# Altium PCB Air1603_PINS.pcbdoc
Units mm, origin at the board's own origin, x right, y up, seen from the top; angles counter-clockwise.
Board outline 36.6 x 36.59 mm, 2 copper layers (Top Layer, Bottom Layer); 1 components, 0 nets, 64 pads, 0 vias.
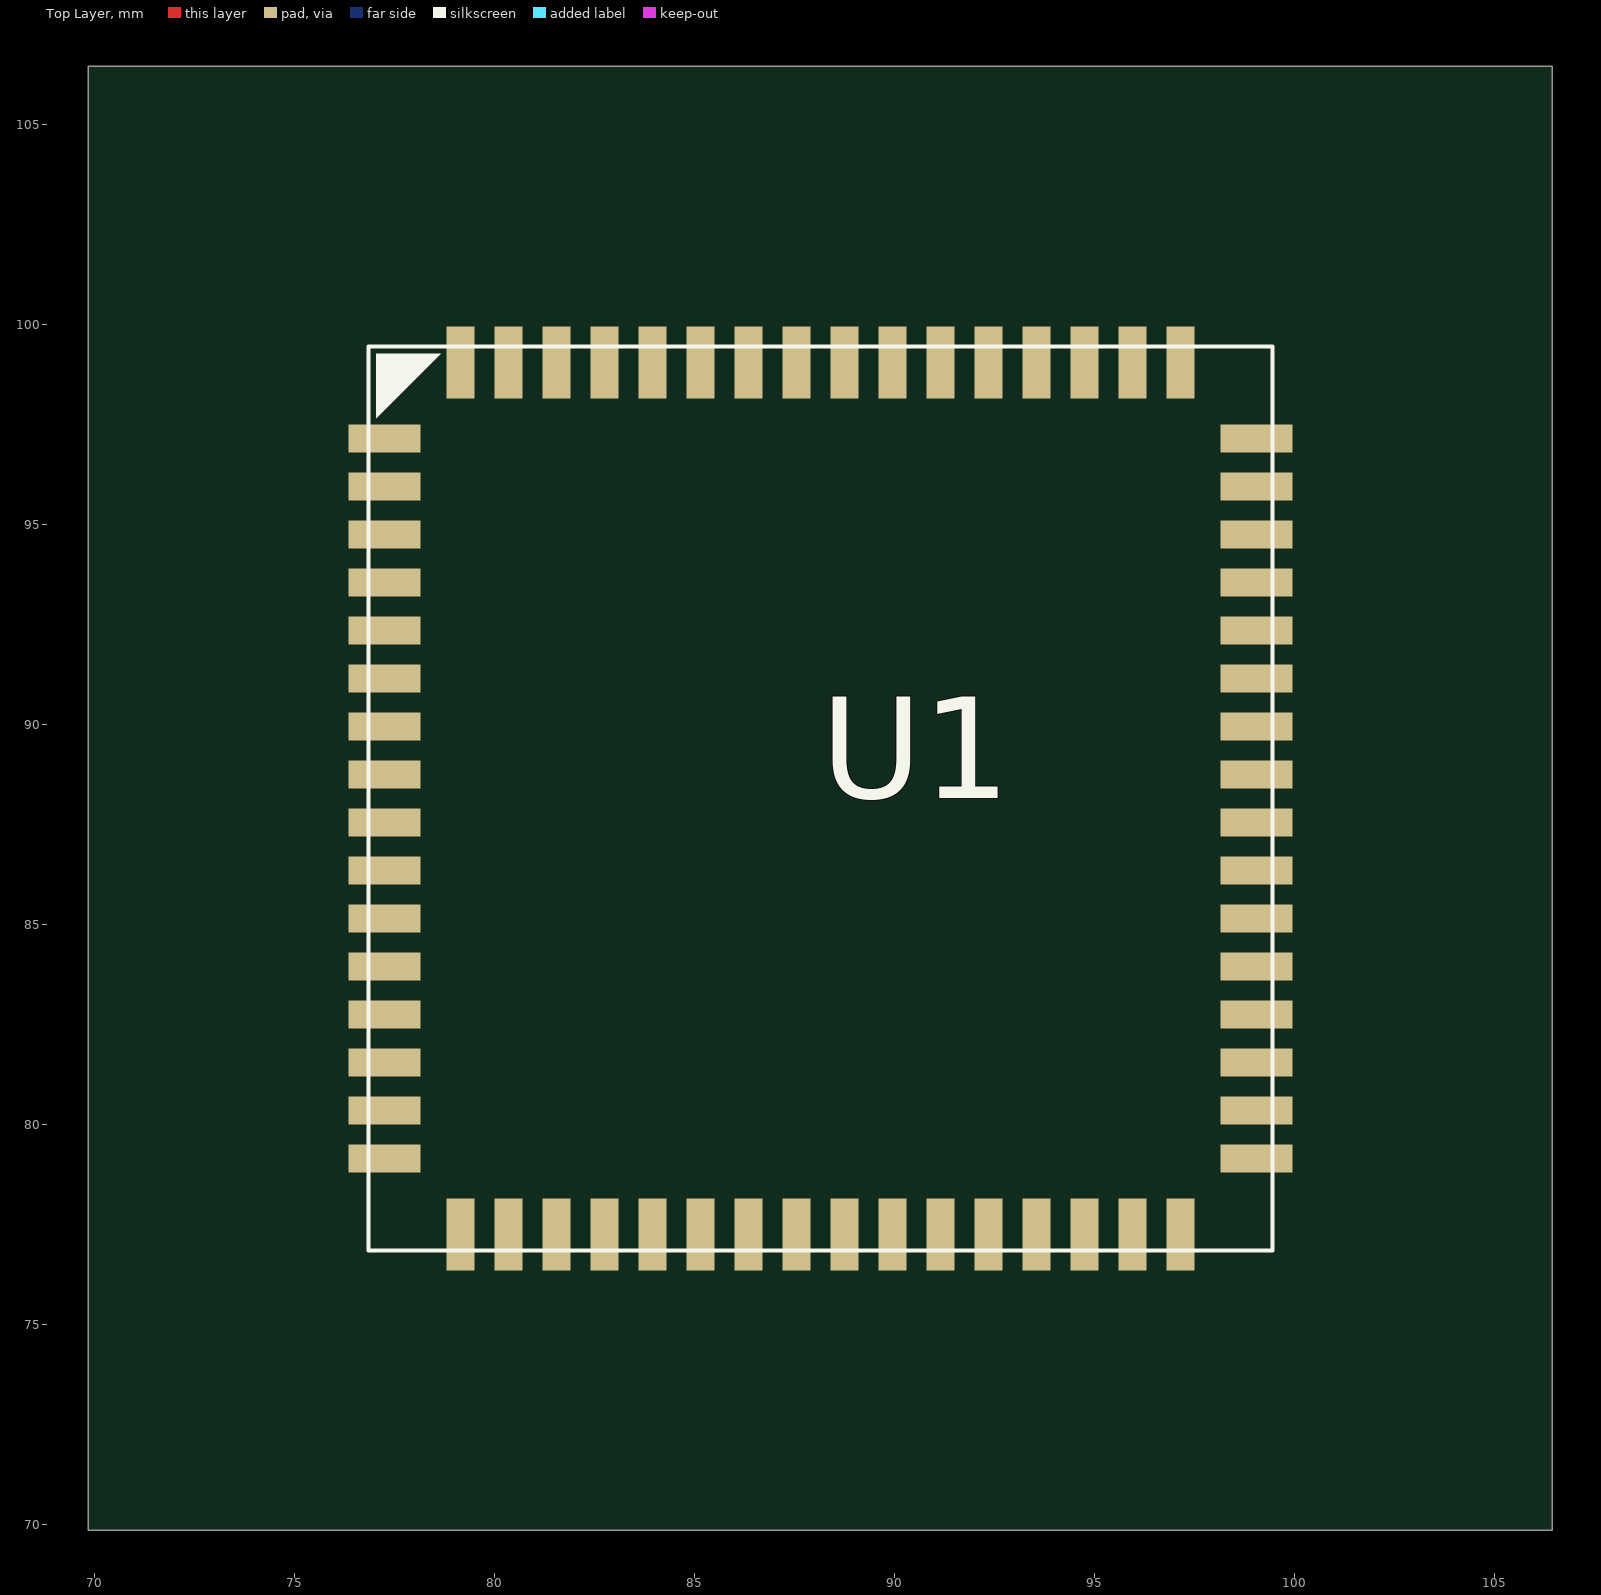
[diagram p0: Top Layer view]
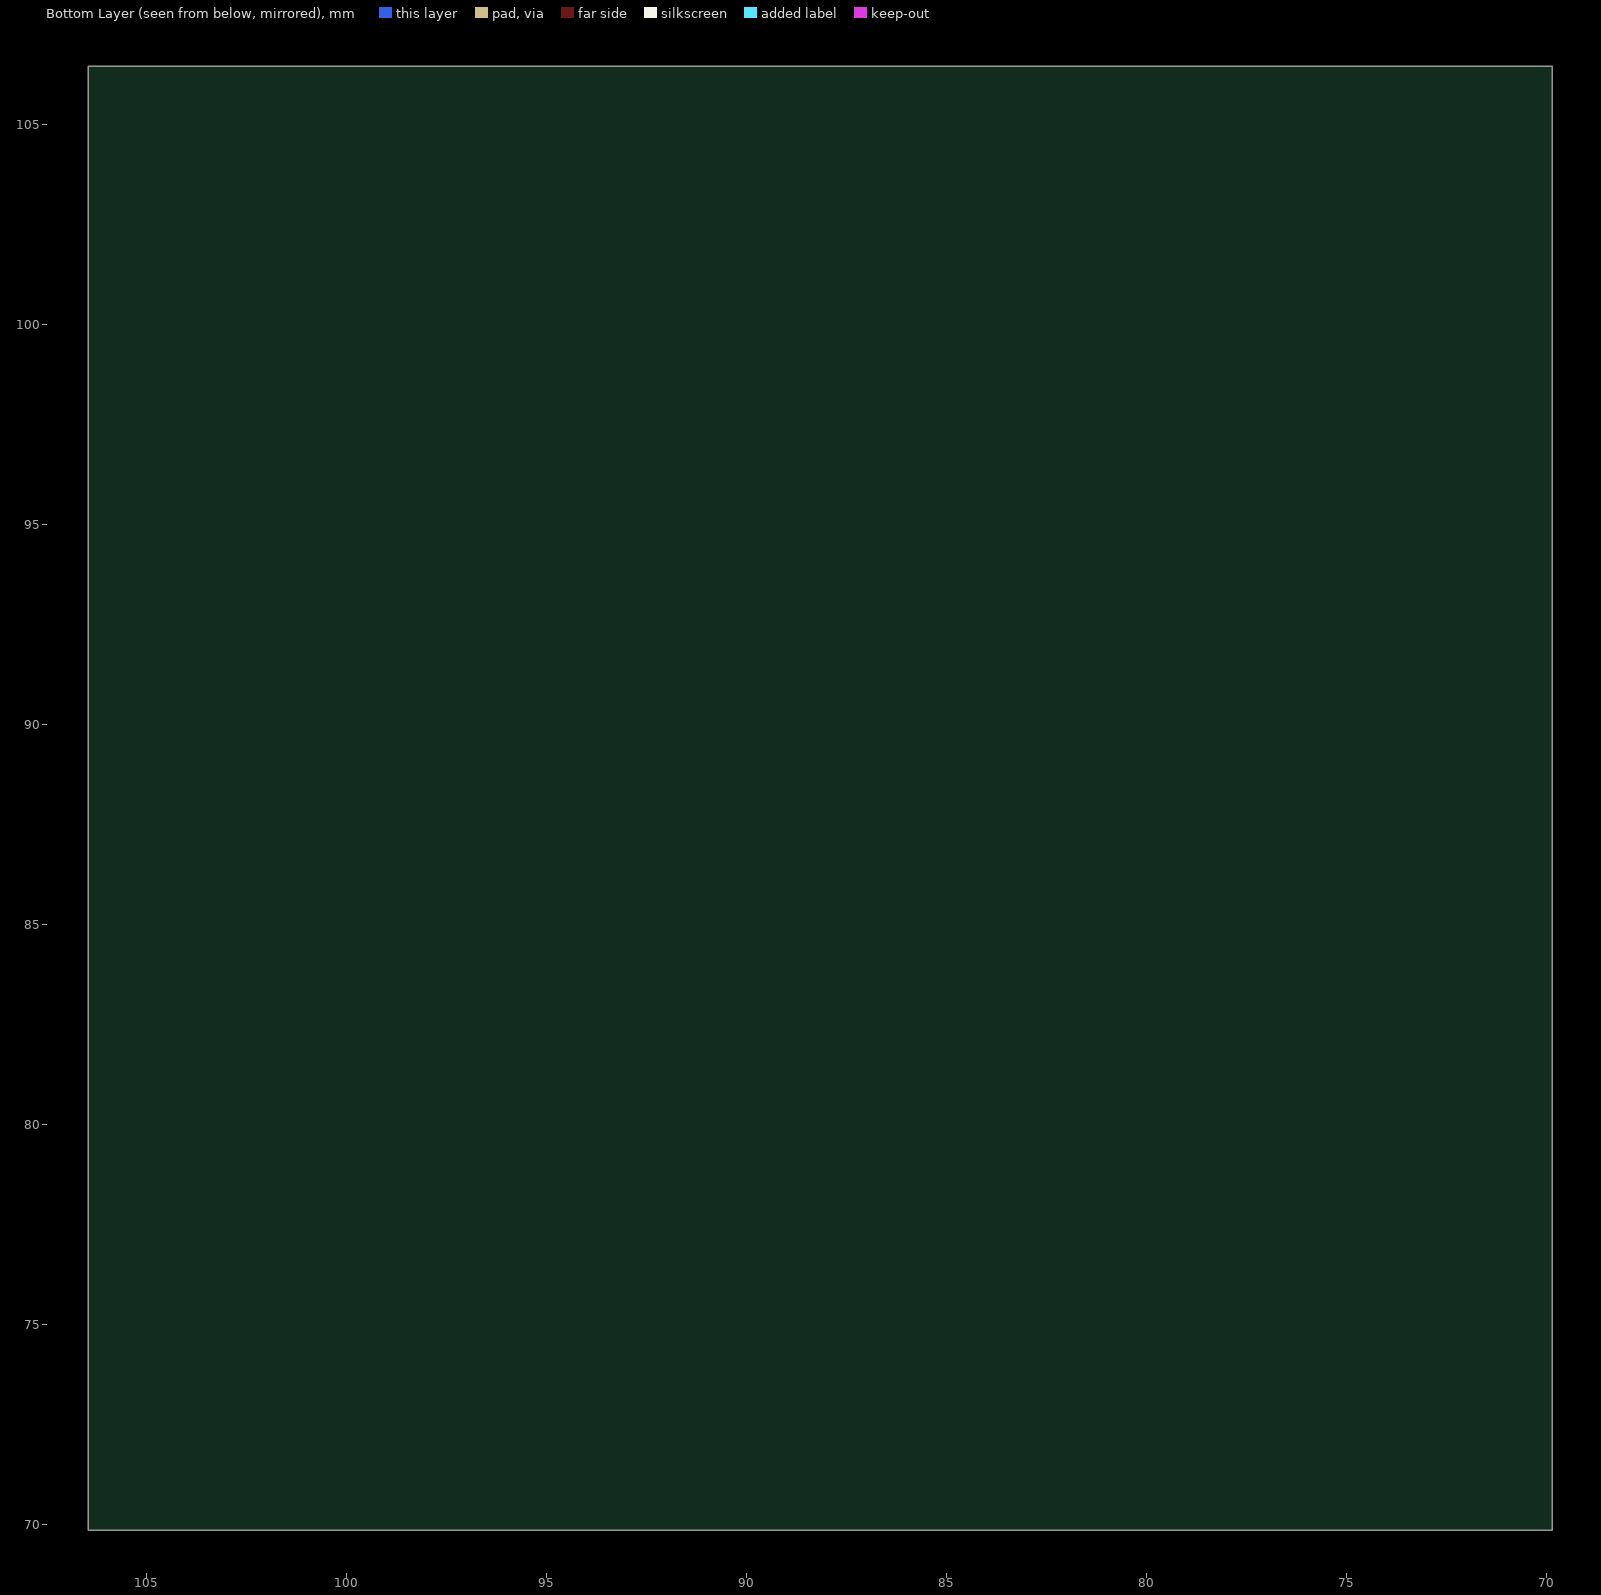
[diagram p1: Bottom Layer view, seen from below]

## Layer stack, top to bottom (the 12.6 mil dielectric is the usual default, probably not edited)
Top Layer: signal copper (thickness not stored)
Dielectric: dielectric 0.32, FR-4, Dk 4.8
Bottom Layer: signal copper (thickness not stored)

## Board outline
106.453,69.85 69.85,69.85 69.85,106.444 106.453,106.444

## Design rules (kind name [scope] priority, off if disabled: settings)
BoardOutlineClearance safeClearance [All] p0: genericclearance=0.254 ignorepadtopadclearanceinfootprint=FALSE except(0: Region-OutlineEdge Poly-OutlineEdge Text-OutlineEdge Sheet-OutlineEdge Hole-OutlineEdge Track-CutoutEdge SMDPad-CutoutEdge THPad-CutoutEdge Via-CutoutEdge Fill-CutoutEdge Region-CutoutEdge Poly-CutoutEdge Text-CutoutEdge Sheet-CutoutEdge Hole-CutoutEdge Arc-SplitContinuation Track-SplitContinuation SMDPad-SplitContinuation THPad-SplitContinuation Via-SplitContinuation Fill-SplitContinuation Poly-SplitContinuation Region-SplitContinuation Text-SplitContinuation; 0.152: Track-OutlineEdge SMDPad-OutlineEdge THPad-OutlineEdge Via-OutlineEdge Fill-OutlineEdge)
Clearance safeClearance [All] p1: gap=0.178 ignorepadtopadclearanceinfootprint=FALSE except(0: Region-Track Poly-Track Region-SMDPad Poly-SMDPad Region-THPad Poly-THPad Region-Via Poly-Via Region-Fill Poly-Fill Text-Fill Track-Region SMDPad-Region THPad-Region Via-Region Fill-Region Region-Region Poly-Region Text-Region Sheet-Region Hole-Region Track-Poly SMDPad-Poly THPad-Poly Via-Poly Fill-Poly Region-Poly Poly-Poly Text-Poly Sheet-Poly Hole-Poly Fill-Text Region-Text Poly-Text Text-Text Sheet-Text Hole-Text Region-Sheet Poly-Sheet Text-Sheet Sheet-Sheet Hole-Sheet Region-Hole Poly-Hole Text-Hole Sheet-Hole; 0.152: Track-Track SMDPad-Track THPad-Track Via-Track Fill-Track Text-Track Sheet-Track Hole-Track Track-SMDPad SMDPad-SMDPad THPad-SMDPad Via-SMDPad Fill-SMDPad Text-SMDPad Sheet-SMDPad Hole-SMDPad Track-THPad SMDPad-THPad THPad-THPad Via-THPad Fill-THPad Text-THPad Sheet-THPad Hole-THPad Track-Via SMDPad-Via THPad-Via Via-Via Fill-Via Text-Via Sheet-Via Hole-Via Track-Fill SMDPad-Fill THPad-Fill Via-Fill Fill-Fill Sheet-Fill Hole-Fill Track-Text SMDPad-Text THPad-Text Via-Text Track-Sheet SMDPad-Sheet THPad-Sheet Via-Sheet Fill-Sheet Track-Hole SMDPad-Hole THPad-Hole Via-Hole Fill-Hole Hole-Hole)
PasteMaskExpansion Common [All] p1: expansion=0
SolderMaskExpansion Common [All] p1: useseparateexpansions=TRUE expansion=0 expansionbottom=0
Width trackWidth [All] p1: maxlimit=12 minlimit=12 preferedwidth=12

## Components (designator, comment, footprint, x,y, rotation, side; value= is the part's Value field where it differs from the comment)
U1 "AIR1603_PINS" AIR1603_PINS 88.157,88.141 r0 top

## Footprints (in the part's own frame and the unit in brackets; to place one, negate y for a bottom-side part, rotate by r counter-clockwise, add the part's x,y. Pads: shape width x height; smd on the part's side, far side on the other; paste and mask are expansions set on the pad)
AIR1603_PINS [mm]
  rect 1.8x0.7 smd: 1(-10.9,9) 2(-10.9,7.8) 3(-10.9,6.6) 4(-10.9,5.4) 5(-10.9,4.2) 6(-10.9,3) 7(-10.9,1.8) 8(-10.9,0.6) 9(-10.9,-0.6) 10(-10.9,-1.8) 11(-10.9,-3) 12(-10.9,-4.2) 13(-10.9,-5.4) 14(-10.9,-6.6) 15(-10.9,-7.8) 16(-10.9,-9) 33(10.9,-9) 34(10.9,-7.8) 35(10.9,-6.6) 36(10.9,-5.4) 37(10.9,-4.2) 38(10.9,-3) 39(10.9,-1.8) 40(10.9,-0.6) 41(10.9,0.6) 42(10.9,1.8) 43(10.9,3) 44(10.9,4.2) 45(10.9,5.4) 46(10.9,6.6) 47(10.9,7.8) 48(10.9,9)
  rect 0.7x1.8 smd: 17(-9,-10.9) 18(-7.8,-10.9) 19(-6.6,-10.9) 20(-5.4,-10.9) 21(-4.2,-10.9) 22(-3,-10.9) 23(-1.8,-10.9) 24(-0.6,-10.9) 25(0.6,-10.9) 26(1.8,-10.9) 27(3,-10.9) 28(4.2,-10.9) 29(5.4,-10.9) 30(6.6,-10.9) 31(7.8,-10.9) 32(9,-10.9) 49(9,10.9) 50(7.8,10.9) 51(6.6,10.9) 52(5.4,10.9) 53(4.2,10.9) 54(3,10.9) 55(1.8,10.9) 56(0.6,10.9) 57(-0.6,10.9) 58(-1.8,10.9) 59(-3,10.9) 60(-4.2,10.9) 61(-5.4,10.9) 62(-6.6,10.9) 63(-7.8,10.9) 64(-9,10.9)
  silkscreen extent -11.3,-11.3 11.3,11.3

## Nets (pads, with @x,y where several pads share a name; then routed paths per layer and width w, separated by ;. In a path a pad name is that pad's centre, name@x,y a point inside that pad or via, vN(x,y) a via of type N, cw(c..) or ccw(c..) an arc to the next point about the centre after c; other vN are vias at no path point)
pads on no net: U1.1 U1.2 U1.3 U1.4 U1.5 U1.6 U1.7 U1.8 U1.9 U1.10 U1.11 U1.12 U1.13 U1.14 U1.15 U1.16 U1.17 U1.18 U1.19 U1.20 U1.21 U1.22 U1.23 U1.24 U1.25 U1.26 U1.27 U1.28 U1.29 U1.30 U1.31 U1.32 U1.33 U1.34 U1.35 U1.36 U1.37 U1.38 U1.39 U1.40 U1.41 U1.42 U1.43 U1.44 U1.45 U1.46 U1.47 U1.48 U1.49 U1.50 U1.51 U1.52 U1.53 U1.54 U1.55 U1.56 U1.57 U1.58 U1.59 U1.60 U1.61 U1.62 U1.63 U1.64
